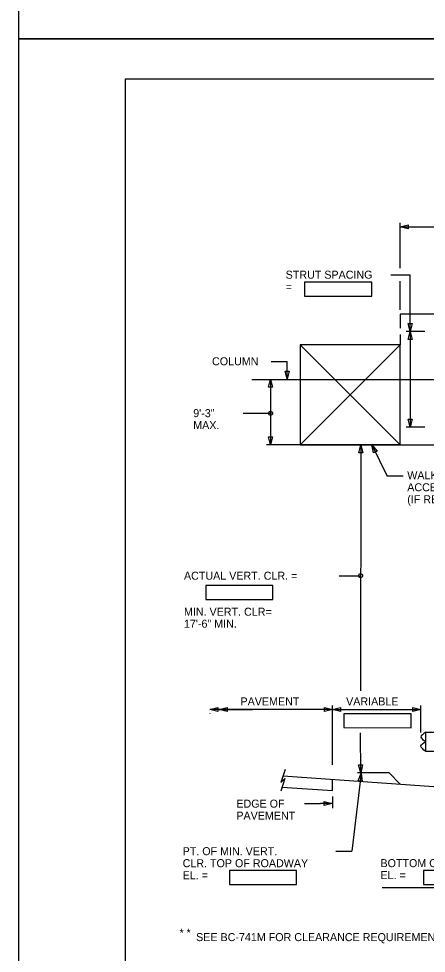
# Model space of a CAD drawing. Extents: x 3829340 to 3831660, y 499389 to 501171.
# Drawn here: x 3829340 to 3829492.7, y 499640.3 to 499990.7 of the extents above; entities that cross this region are included whole.
import ezdxf

# ---------------------------------------------------------------- set-up
doc = ezdxf.new("R2010")
doc.units = 0
for name, color, linetype in [('2', 7, 'Continuous'), ('CNTR', 7, 'Continuous'), ('Default', 7, 'Continuous'), ('DIM TXT', 7, 'Continuous'), ('grade', 7, 'Continuous'), ('PLT-BNDY', 7, 'Continuous'), ('sign', 7, 'Continuous')]:
    doc.layers.add(name, color=color, linetype=linetype)

msp = doc.modelspace()

# ---------------------------------------------------------------- linework, layer by layer
at = {"layer": '2'}
for p, q in [((3829379.96, 499404.19), (3829379.96, 499968.19)), ((3829379.96, 499968.19), (3830165.96, 499968.19))]:
    msp.add_line(p, q, dxfattribs=at)
at = {"layer": 'CNTR'}
msp.add_line((3829427.35, 499855.45), (3829712.05, 499855.45), dxfattribs=at)
at = {"layer": 'Default'}
msp.add_lwpolyline([(3829439.82, 499709.12), (3829438.13, 499704.34), (3829439.73, 499705.75), (3829438.13, 499701)], dxfattribs=at)
at = {"layer": 'DIM TXT'}
for p, q in [((3829482.91, 499897.14), (3829482.91, 499914.2)), ((3829482.91, 499912.7), (3829637.64, 499912.7)), ((3829479.34, 499894.7), (3829486.69, 499894.7)), ((3829486.69, 499873.42), (3829486.69, 499894.7)), ((3829482.91, 499881.47), (3829482.91, 499892.29)), ((3829492.17, 499873.42), (3829485.19, 499873.42)), ((3829486.69, 499873.42), (3829486.69, 499837.49)), ((3829434.53, 499862.17), (3829440.53, 499862.17)), ((3829440.53, 499855.49), (3829440.53, 499862.17)), ((3829432.83, 499855.49), (3829432.83, 499855.49)), ((3829434.33, 499855.49), (3829434.33, 499830.94)), ((3829424.07, 499842.78), (3829430.07, 499842.78)), ((3829430.07, 499842.78), (3829434.63, 499842.78)), ((3829492.17, 499837.49), (3829485.19, 499837.49)), ((3829447.63, 499830.94), (3829432.83, 499830.94)), ((3829468.11, 499830.94), (3829467.96, 499738.72)), ((3829472.23, 499830.94), (3829478.04, 499819.1)), ((3829484.04, 499819.1), (3829478.04, 499819.1)), ((3829459.98, 499781.83), (3829465.98, 499781.83)), ((3829465.98, 499781.83), (3829468.06, 499781.83)), ((3829457.47, 499710.88), (3829457.47, 499733.2)), ((3829457.49, 499728.89), (3829457.49, 499733.2)), ((3829490.63, 499723.03), (3829490.63, 499733.2)), ((3829457.49, 499731.7), (3829411.62, 499731.7)), ((3829411.62, 499730.23), (3829411.62, 499730.2)), ((3829415.06, 499731.7), (3829427.56, 499731.7)), ((3829433.56, 499731.7), (3829427.56, 499731.7)), ((3829457.47, 499731.7), (3829490.63, 499731.7)), ((3829468.09, 499707.9), (3829468, 499722.97)), ((3829468.25, 499707.85), (3829464.77, 499678.54)), ((3829457.47, 499699.08), (3829457.47, 499694.7)), ((3829447.01, 499696.37), (3829453.01, 499696.37)), ((3829457.43, 499696.38), (3829453.01, 499696.37)), ((3829458.77, 499678.54), (3829464.77, 499678.54)), ((3829476.2, 499664.88), (3829527.52, 499664.88))]:
    msp.add_line(p, q, dxfattribs=at)
for points in [[(3829485.91, 499911.95), (3829482.91, 499912.7), (3829485.91, 499913.45)], [(3829447.08, 499886.61), (3829472.27, 499886.61), (3829472.27, 499891.86), (3829447.08, 499891.86)], [(3829487.44, 499876.42), (3829486.69, 499873.42), (3829485.94, 499876.42)], [(3829485.94, 499870.42), (3829486.69, 499873.42), (3829487.44, 499870.42)], [(3829441.28, 499858.49), (3829440.53, 499855.49), (3829439.78, 499858.49)], [(3829433.58, 499852.49), (3829434.33, 499855.49), (3829435.08, 499852.49)], [(3829487.44, 499840.49), (3829486.69, 499837.49), (3829485.94, 499840.49)], [(3829435.08, 499833.94), (3829434.33, 499830.94), (3829433.58, 499833.94)], [(3829467.35, 499827.95), (3829468.11, 499830.94), (3829468.85, 499827.94)], [(3829472.88, 499827.92), (3829472.23, 499830.94), (3829474.23, 499828.58)], [(3829410.04, 499772.96), (3829435.23, 499772.96), (3829435.23, 499778.21), (3829410.04, 499778.21)], [(3829414.62, 499730.95), (3829411.62, 499731.7), (3829414.62, 499732.45)], [(3829418.06, 499730.95), (3829415.06, 499731.7), (3829418.06, 499732.45)], [(3829454.49, 499732.45), (3829457.49, 499731.7), (3829454.49, 499730.95)], [(3829460.47, 499730.95), (3829457.47, 499731.7), (3829460.47, 499732.45)], [(3829487.63, 499732.45), (3829490.63, 499731.7), (3829487.63, 499730.95)], [(3829461.76, 499724.86), (3829486.95, 499724.85), (3829486.95, 499730.1), (3829461.76, 499730.1)], [(3829468.83, 499710.91), (3829468.09, 499707.9), (3829467.33, 499710.9)], [(3829467.15, 499704.95), (3829468.25, 499707.85), (3829468.64, 499704.78)], [(3829454.42, 499697.12), (3829457.43, 499696.38), (3829454.43, 499695.62)], [(3829418.88, 499666.04), (3829444.07, 499666.04), (3829444.07, 499671.29), (3829418.88, 499671.29)], [(3829491.67, 499666.04), (3829516.86, 499666.04), (3829516.86, 499671.29), (3829491.67, 499671.29)]]:
    msp.add_lwpolyline(points, close=True, dxfattribs=at)
for centre in [(3829434.32, 499842.74), (3829468.03, 499781.83)]:
    msp.add_circle(centre, 0.75, dxfattribs=at)
at = {"layer": 'grade'}
for p, q in [((3829478.72, 499707.89), (3829466.85, 499707.89)), ((3829482.9, 499703.71), (3829478.72, 499707.89)), ((3829439.08, 499706.78), (3829573.55, 499697.34)), ((3829457.47, 499701.27), (3829457.47, 499705.46)), ((3829438.73, 499702.59), (3829457.47, 499701.27))]:
    msp.add_line(p, q, dxfattribs=at)
msp.add_lwpolyline([(3829496.1, 499723.18), (3829496.1, 499715.93), (3829492.47, 499715.93), (3829492.47, 499723.18)], close=True, dxfattribs=at)
for points in [[(3829492.47, 499723.18), (3829490.68, 499721.29), (3829492.46, 499719.64)], [(3829492.47, 499715.93), (3829490.68, 499718), (3829492.46, 499719.64)]]:
    msp.add_spline(points, degree=3, dxfattribs=at)
at = {"layer": 'PLT-BNDY'}
for points in [[(3829339.96, 500577.19), (3830180.96, 500577.19), (3830180.96, 499983.19), (3829339.96, 499983.19)], [(3829339.96, 499983.19), (3830180.96, 499983.19), (3830180.96, 499389.19), (3829339.96, 499389.19)]]:
    msp.add_lwpolyline(points, close=True, dxfattribs=at)
at = {"layer": 'sign'}
for p, q in [((3829637.63, 499879.96), (3829482.91, 499879.96)), ((3829482.91, 499879.96), (3829482.91, 499874.71)), ((3829482.91, 499872.32), (3829482.91, 499868.44)), ((3829482.91, 499830.94), (3829637.63, 499830.94))]:
    msp.add_line(p, q, dxfattribs=at)
msp.add_lwpolyline([(3829445.41, 499830.94), (3829482.91, 499830.94), (3829482.91, 499868.44), (3829445.41, 499868.44)], close=True, dxfattribs=at)
msp.add_lwpolyline([(3829445.41, 499868.44), (3829482.91, 499830.94), (3829445.41, 499830.94), (3829482.91, 499868.44)], dxfattribs=at)

# ---------------------------------------------------------------- texts
at = {"layer": 'DIM TXT'}
for s, height, p in [('STRUT SPACING', 2.9999, (3829439.98, 499893.2)), ('=', 3, (3829439.98, 499888.7)), ('  COLUMN', 3, (3829410.17, 499860.73)), ('9\'-3"', 3, (3829405.35, 499841.28)), ('MAX.', 3, (3829405.35, 499836.78)), ('WALK-IN (ONE END ONLY)', 2.9999, (3829485.54, 499817.99)), ('ACCESS PLATFORM', 2.9999, (3829485.54, 499813.49)), ('(IF REQUIRED)', 2.9999, (3829485.54, 499808.99)), ('ACTUAL VERT. CLR. =', 2.9999, (3829401.88, 499780.33)), ('MIN. VERT. CLR=', 2.9999, (3829401.88, 499766.83)), ('17\'-6" MIN.', 2.9999, (3829401.88, 499762.33)), ('PAVEMENT', 3, (3829423.06, 499733.2)), ('VARIABLE', 3, (3829462.63, 499733.2)), ('EDGE OF', 3, (3829421.51, 499694.87)), ('PAVEMENT', 3, (3829421.51, 499690.37)), ('PT. OF MIN. VERT.', 2.9999, (3829401.38, 499677.04)), ('CLR. TOP OF ROADWAY', 2.9999, (3829401.38, 499672.54)), ('BOTTOM OF FOOTING', 2.9999, (3829475.5, 499672.56)), ('EL. =', 3, (3829401.38, 499668.04)), ('EL. =', 3, (3829475.5, 499668.06)), ('*', 3, (3829400.24, 499646.47)), ('*', 3, (3829402.86, 499646.51)), ('SEE BC-741M FOR CLEARANCE REQUIREMENTS.', 2.9999, (3829406.43, 499644.82))]:
    msp.add_text(s, height=height, dxfattribs=at).set_placement(p)

doc.saveas('drawing.dxf')
